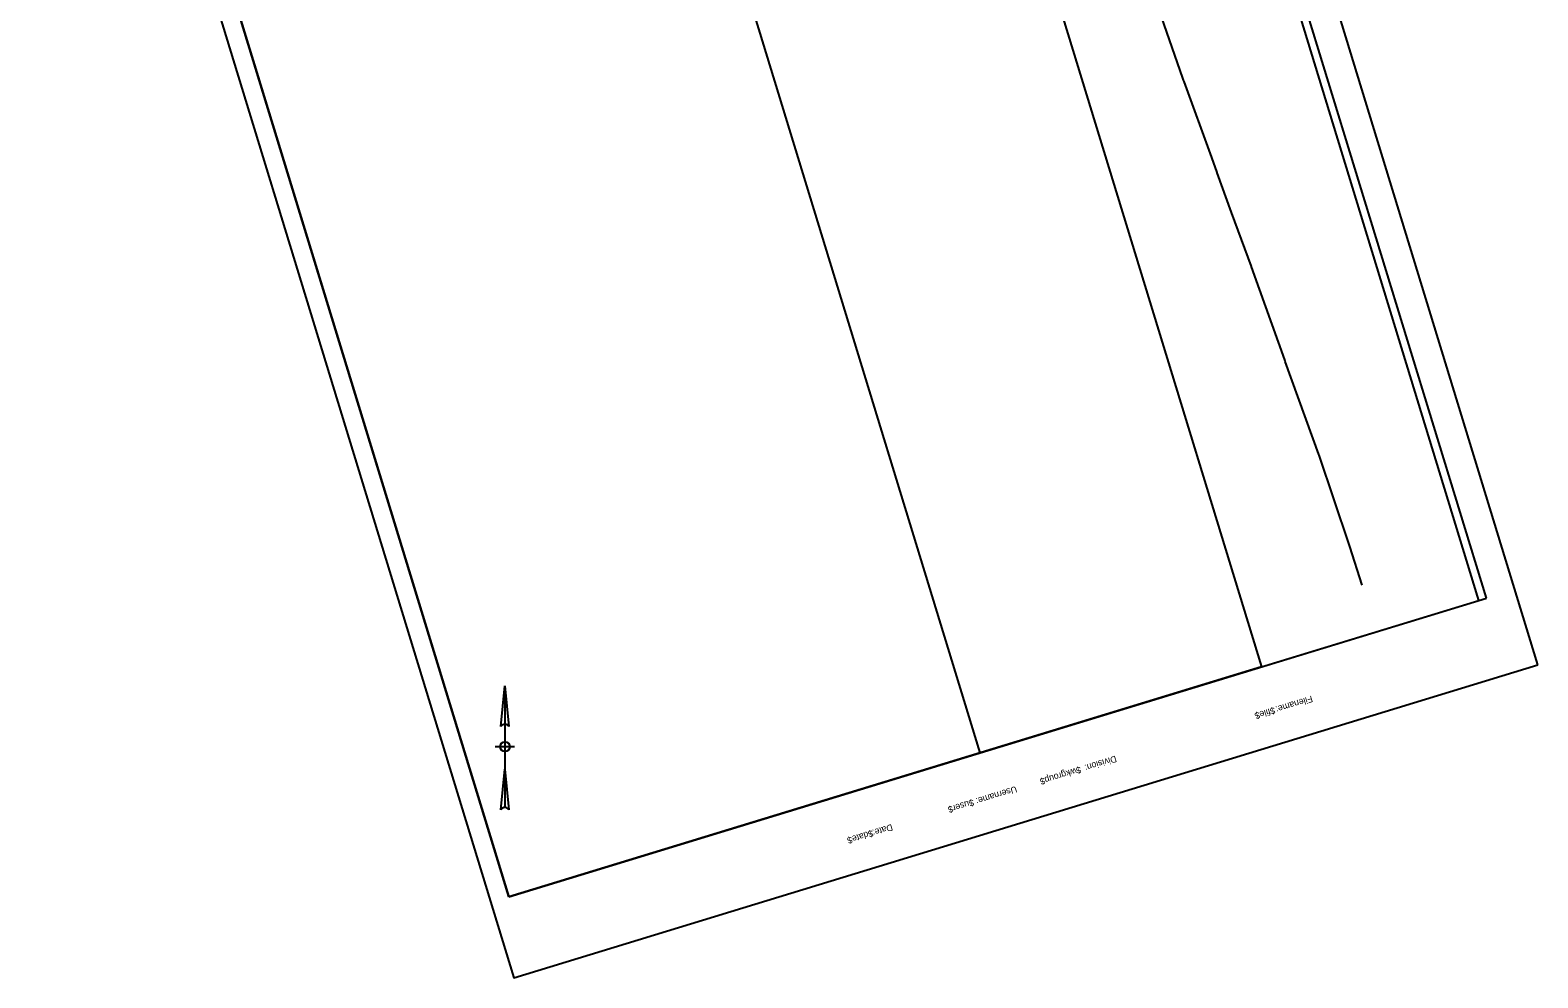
# Model space of a CAD drawing. Extents: x 1038073 to 1038848, y 778999 to 779973.
# Drawn here: x 1038073 to 1038848, y 778999 to 779486 of the extents above; entities that cross this region are included whole.
import ezdxf

# ---------------------------------------------------------------- set-up
doc = ezdxf.new("R2010")
doc.units = 0
for name, color, linetype in [('CLIPS', 7, 'Continuous'), ('D_Roadway_Centerline', 7, 'Continuous'), ('Default', 7, 'Continuous'), ('PLOT BOUNDARY', 7, 'Continuous')]:
    doc.layers.add(name, color=color, linetype=linetype)

msp = doc.modelspace()

# ---------------------------------------------------------------- linework, layer by layer
at = {"layer": 'CLIPS'}
for points in [[(1038817.65, 779193.13), (1038598.37, 779910.36), (1038342.08, 779832), (1038561.36, 779114.78)], [(1038319.41, 779040.8), (1038100.13, 779758.03), (1038486.62, 779876.19), (1038705.9, 779158.97)]]:
    msp.add_lwpolyline(points, close=True, dxfattribs=at)
at = {"layer": 'D_Roadway_Centerline'}
msp.add_lwpolyline([(1038757.7, 779200.92), (1038751.34, 779220.91), (1038751.01, 779221.88), (1038751.01, 779221.88), (1038735.54, 779267.8), (1038735.44, 779268.07), (1038718.2, 779315.93), (1038717.91, 779316.73), (1038704.95, 779352.99), (1038700.84, 779364.57), (1038700.78, 779364.74), (1038690.64, 779392.48), (1038683.24, 779412.79), (1038683.18, 779412.96), (1038680.4, 779420.6), (1038666.23, 779459.72), (1038665.97, 779460.41), (1038665.63, 779461.39), (1038649.2, 779508.82)], dxfattribs=at)
at = {"layer": 'Default'}
for p, q in [((1038821.47, 779194.3), (1038587.57, 779959.34)), ((1038085.51, 779805.85), (1038319.41, 779040.8)), ((1038319.41, 779040.8), (1038821.47, 779194.3)), ((1038315.23, 779128.44), (1038317.31, 779149.28)), ((1038317.31, 779149.28), (1038317.31, 779086.78)), ((1038317.31, 779149.28), (1038319.4, 779128.44)), ((1038312.31, 779118.03), (1038322.31, 779118.03)), ((1038315.23, 779085.66), (1038317.31, 779106.49)), ((1038317.31, 779106.49), (1038319.4, 779085.66))]:
    msp.add_line(p, q, dxfattribs=at)
msp.add_circle((1038317.31, 779118.03), 2.5, dxfattribs=at)
for centre in [(1038317.31, 779127.06), (1038317.31, 779084.28)]:
    msp.add_arc(centre, 2.5, 33.55731, 146.44269, dxfattribs=at)
at = {"layer": 'PLOT BOUNDARY'}
msp.add_lwpolyline([(1038847.92, 779160.07), (1038599.41, 779972.93), (1038073.44, 779812.13), (1038321.96, 778999.27)], close=True, dxfattribs=at)

# ---------------------------------------------------------------- texts
at = {"layer": 'Default'}
for s, p in [('$file$', (1038712.42, 779138.4)), ('Filename:', (1038731.67, 779144.29)), ('$wkgroup$', (1038612.75, 779107.93)), ('Division:', (1038630.94, 779113.49)), ('$user$', (1038557.66, 779091.08)), ('Username:', (1038579.77, 779097.84)), ('$date$', (1038505.95, 779075.28)), ('Date:', (1038515.94, 779078.33))]:
    msp.add_text(s, height=3.348, rotation=197, dxfattribs=at).set_placement(p)

doc.saveas('drawing.dxf')
